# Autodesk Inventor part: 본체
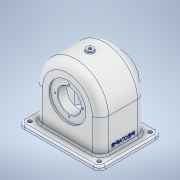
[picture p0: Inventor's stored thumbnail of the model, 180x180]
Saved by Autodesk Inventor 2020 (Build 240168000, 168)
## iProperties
Created: 2022-09
Part Number: 본체
Material: 알루미늄 6061
Document SubType Name: Modeling
Designer: Administrator
Density: 2.7 g/cm^3
Appearance: 알루미늄 - 평지
Mass: 785.035 g
Surface Area: 1042.06 cm^2
Volume: 290.754 cm^3
Author: Administrator
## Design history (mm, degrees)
sketch "스케치2" dims "d2" = 114
  geometry: L1 (-57, 32)-(57, 32); L2 (57, 32)-(57, -32); L3 (57, -32)-(-57, -32); L4 (-57, -32)-(-57, 32); L5 (-57, 32)-(57, -32); L6 (57, 32)-(-57, -32); 3 further points
  constraints: 12 end point, 3 midpoint, 2 parallel, 1 horizontal, 1 perpendicular, 3 other
  dimensions: "d3" = 64 distance between parallel lines of L3 L1
extrude "돌출1" new body sketch "스케치2" stored distance "d4" = 78; taper "d5" = 0 deg
feature "쉘1" dims "d17" = 5
sketch "스케치5"
  geometry: L1 (114, -78)-(114, 0) reference; L2 (0, 0)-(114, 0) reference; L3 (0, -78)-(0, 0) reference; L4 (114, -78)-(0, -78) reference; L5 (117, 15)-(-3, 15); L6 (-13, 5)-(-13, -83); L7 (-3, -93)-(117, -93); L8 (127, -83)-(127, 5); L9 (127, 15)-(-13, -93); L10 (-13, 15)-(127, -93); C1 r 3.3 at (117, 5); C2 r 3.3 at (117, -83); C3 r 3.3 at (-3, -83); C4 r 3.3 at (-3, 5); A1 r 10 centre (117, 5) between (127, 5) and (117, 15); A2 r 10 centre (117, -83) between (117, -93) and (127, -83); A3 r 10 centre (-3, -83) between (-13, -83) and (-3, -93); A4 r 10 centre (-3, 5) between (-3, 15) and (-13, 5); 1 further point
  constraints: 12 end point, 8 centre point, 8 point on circle, 8 point on line, 8 tangent, 3 equal radius, 2 midpoint, 2 parallel, 1 coincident, 1 horizontal, 1 perpendicular
  dimensions: "d18" = 140 distance of L9.start L10.start; "d19" = 108 distance of L10.end L9.start; "d20" = 10 radius of A1; "d21" = 6.6 diameter of C1; "d22" = 6.6 diameter of C2; "d23" = 6.6 diameter of C3; "d24" = 6.6 diameter of C4
extrude "돌출3" join sketch "스케치5" distance "d25" = 7; taper "d26" = 0 deg
sketch "스케치6"
  geometry: L1 (32, 67.171)-(32, -65.92); L2 (-32, -47.3)-(-32, -40.7) reference; L3 (89, 39)-(32, 39) reference; L4 (32, 39)-(60, 39); L5 (60, 39)-(60, 20); L6 (60, 20)-(32, 20); L7 (32, 20)-(32, 39); L8 (70.97, 39)-(60, 20); L9 (70.97, 39)-(60, 39); L10 (84, 34)-(32, 34) reference; 3 further points
  constraints: 14 end point, 2 parallel, 1 collinear, 1 horizontal, 1 perpendicular, 1 point on line, 1 vertical
  dimensions: "d27" = 64 distance between parallel lines of L2 L1; "d28" = 56 diameter of L5.end L1; "d29" = 60 deg angle of L6 L8; "d30" = 14 distance from line of L10 L5.end
revolve "회전1" sketch "스케치6" stored, may be unused: angle "d31" = 90 deg
sketch "스케치7"
  geometry: A1 r 57 centre (0, 32) between (57, 32) and (-57, 32) reference; 2 further points
  constraints: 1 coincident
hole "구멍1" sketch "스케치7" at (0, 32) diameter "d32" = 40; stored, may be unused: countersink angle "d36" = 90 deg, drill point angle "d38" = 118 deg; dims "d33" = 11, "d34" = 64, "d35" = 3, "d37" = 13
sketch "스케치8"
  geometry: C1 r 31 at (0, 32); A1 r 57 centre (0, 32) between (57, 32) and (-57, 32) reference; 1 further point
  constraints: 1 centre point, 1 coincident
  dimensions: "d39" = 62 diameter of C1
extrude "돌출4" join sketch "스케치8" distance "d40" = 15; taper "d41" = 0 deg
sketch "스케치9"
  geometry: C1 r 31 at (0, 0) reference; 2 further points
  constraints: 1 coincident
hole "구멍2" sketch "스케치9" at (0, 0) diameter "d42" = 35; stored, may be unused: countersink angle "d46" = 90 deg, drill point angle "d48" = 118 deg; dims "d43" = 11, "d44" = 40, "d45" = 16, "d47" = 13
node "작업 평면1"
sketch "스케치10"
  geometry: C1 r 6 at (60, -54); 1 further point
  constraints: 1 centre point, 1 coincident
  dimensions: "d50" = 12 diameter of C1
extrude "돌출5" join sketch "스케치10" stored distance "d51" = 15; taper "d52" = 0 deg
sketch "스케치11"
  geometry: C1 r 6 at (0, 0) reference; 2 further points
  constraints: 1 coincident
hole "구멍3" sketch "스케치11" at (0, 0) diameter "d53" = 5.1881; stored, may be unused: countersink angle "d57" = 90 deg, drill point angle "d59" = 118 deg; dims "d54" = 53.5, "d55" = 40, "d56" = 16, "d58" = 16
fillet "모깎기1" dims "d60" = 14, "d61" = 9, "d62" = 0.6
sketch "스케치12"
  geometry: C1 r 31 at (0, 0) reference; A1 r 24 centre (0, 0) between (0, 24) and (24, 0); 3 further points
  constraints: 4 point on circle, 1 centre point, 1 coincident
  dimensions: "d63" = 48 diameter of A1
hole "구멍4" sketch "스케치12" at (0, 24), (24, 0), (0, -24), (-24, 0) diameter "d64" = 2.459; stored, may be unused: countersink angle "d68" = 90 deg, drill point angle "d70" = 118 deg; dims "d65" = 7, "d66" = 40, "d67" = 16, "d69" = 9
fillet "모깎기2" dims "d71" = 3, "d90" = 1
chamfer "모따기1" distance "d72" = 1; stored, may be unused: second distance "d73" = 2, angle "d74" = 45 deg
chamfer "모따기2" distance "d75" = 1; stored, may be unused: second distance "d76" = 2, angle "d77" = 45 deg
sketch "스케치13"
  geometry: C1 r 1.23 at (0, -24) reference; A1 r 24 centre (0, 0) between (24, 0) and (-24, 0); 3 further points
  constraints: 4 point on circle, 1 centre point, 1 coincident
  dimensions: "d79" = 48 diameter of A1
hole "구멍5" sketch "스케치13" at (24, 0), (-24, 0), (0, 24), (0, -24) diameter "d80" = 2.459; stored, may be unused: countersink angle "d84" = 90 deg, drill point angle "d86" = 118 deg; dims "d81" = 7, "d82" = 40, "d83" = 16, "d85" = 9
sketch "스케치14"
  geometry: L1 (5.498, -36.006)-(44.502, -36.006); L2 (44.502, -36.006)-(44.502, -57.994); L3 (44.502, -57.994)-(5.498, -57.994); L4 (5.498, -57.994)-(5.498, -36.006); L5 (69, -64)-(-19, -64) reference; 3 further points
  constraints: 2 other
  dimensions: "d87" = 17 distance from line of point (25, -47) L5
feature "엠보싱1" sketch "스케치14" dims "d88" = 0.5, "d89" = 0
node "솔리드1"
feature "A9D066F2-1C7D-4E18-AEED-F7BC21143FA4" dims "d80" = 2.459, "d81" = 7, "d82" = 40, "d83" = 16, "d84" = 90 deg, "d85" = 9, "d86" = 118 deg
other parameters: "d49" = -124
